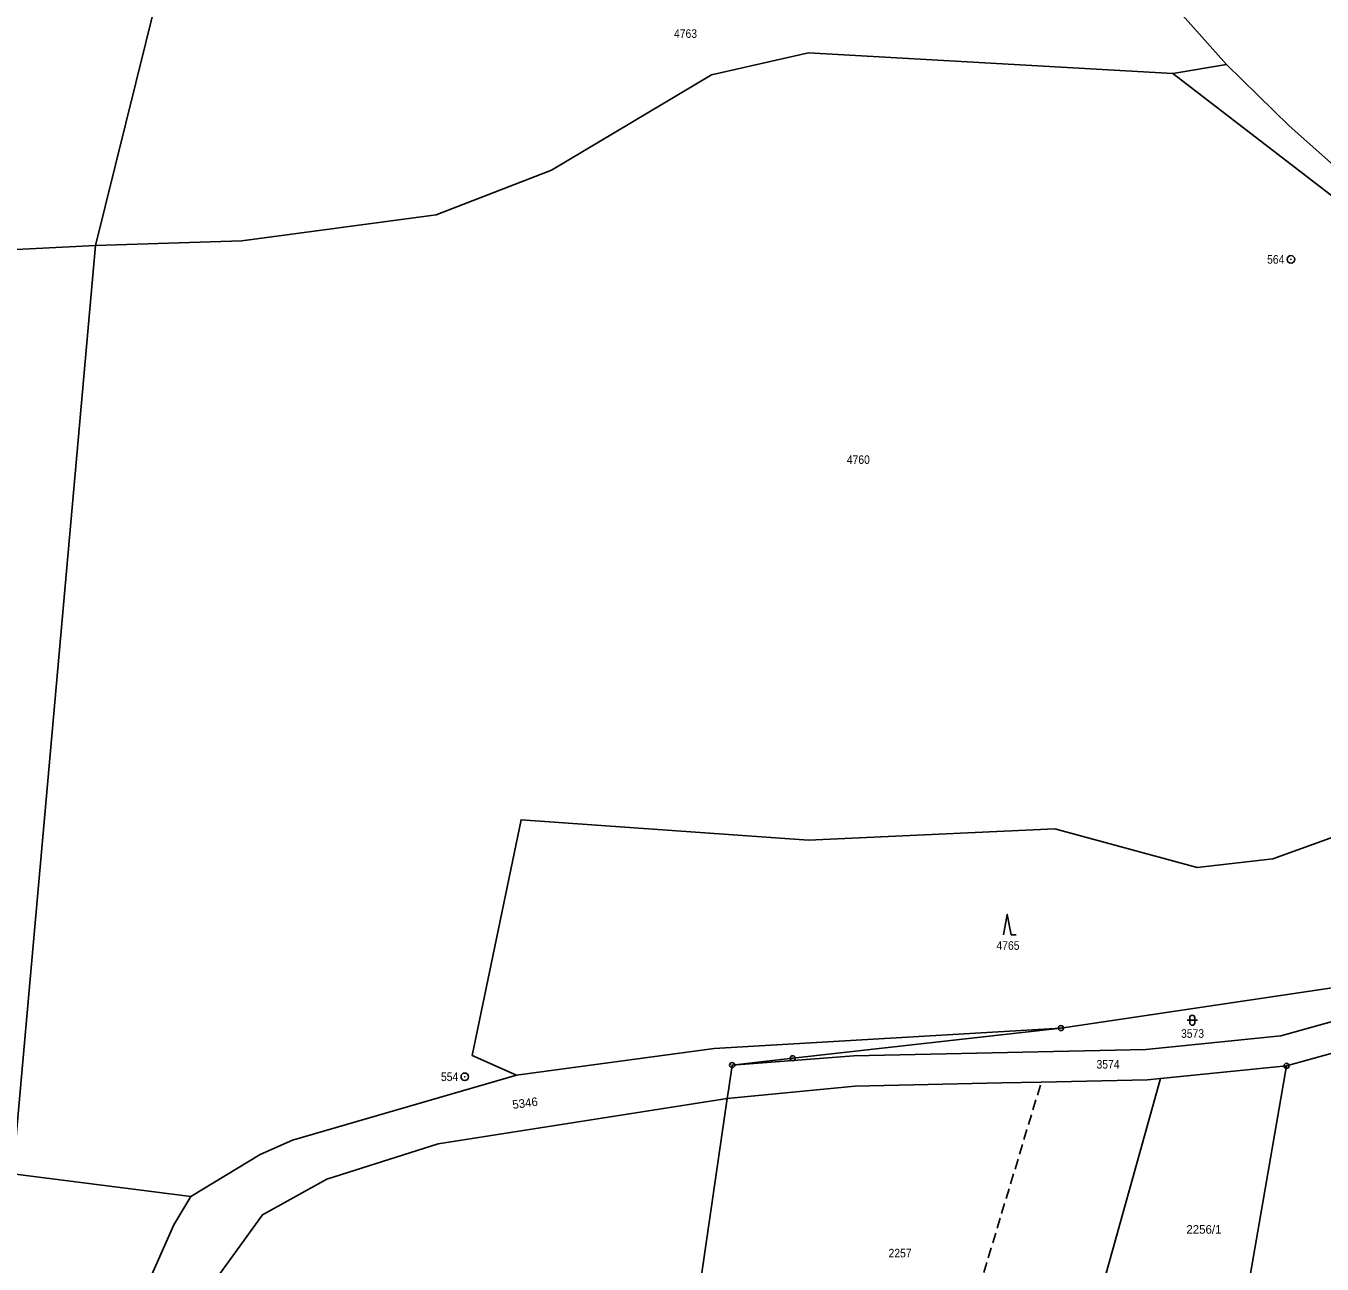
# Model space of a CAD drawing. Extents: x -665688 to -664583, y -1006118 to -1004927.
# Drawn here: x -665448.3 to -665191.6, y -1005645.6 to -1005400.3 of the extents above; entities that cross this region are included whole.
import ezdxf
from ezdxf.enums import TextEntityAlignment as Align

# ---------------------------------------------------------------- set-up
doc = ezdxf.new("R2010")
doc.units = 0
doc.header["$LTSCALE"] = 0.68
doc.linetypes.add('MEDIUM_DASHED', pattern=[4.5, 3, -1.5])
for name, color, linetype, lineweight in [('1', 7, 'Continuous', 25), ('12', 7, 'MEDIUM_DASHED', 25), ('13', 7, 'Continuous', 25), ('24', 7, 'Continuous', 25), ('25', 7, 'Continuous', 25)]:
    doc.layers.add(name, color=color, linetype=linetype, lineweight=lineweight)
doc.layers.add('17', color=7, linetype='Continuous')
doc.layers.add('18', color=7, linetype='Continuous')

msp = doc.modelspace()

# ---------------------------------------------------------------- linework, layer by layer
at = {"layer": '1'}
for p, q in [((-665238, -1005377.08), (-665210.58, -1005407.96)), ((-665434.55, -1005443.84), (-665422.54, -1005395.61)), ((-665308.45, -1005606.17), (-665309.12, -1005610.78)), ((-665223.62, -1005608.84), (-665241.69, -1005673.6)), ((-665309.12, -1005610.78), (-665309.42, -1005612.82))]:
    msp.add_line(p, q, dxfattribs=at)
for points in [[(-665434.55, -1005443.84), (-665405.56, -1005442.93), (-665367.07, -1005437.73), (-665344.22, -1005428.93), (-665312.57, -1005410), (-665293.32, -1005405.67), (-665221.19, -1005409.78)], [(-665136.29, -1005477.24), (-665150.22, -1005460.69), (-665177.15, -1005443.61), (-665221.19, -1005409.78), (-665210.58, -1005407.96)], [(-665210.58, -1005407.96), (-665198.15, -1005420.12), (-665184.6, -1005432.15), (-665168.91, -1005442.94), (-665134.58, -1005458.21), (-665131.02, -1005461.53)], [(-665687.44, -1005437.39), (-665557.36, -1005450.01), (-665434.55, -1005443.84)], [(-665351.13, -1005608.21), (-665395.49, -1005621.05), (-665401.94, -1005623.9), (-665415.62, -1005632.24), (-665450.87, -1005627.72), (-665434.55, -1005443.84)], [(-665160.74, -1005564.98), (-665183.63, -1005558.92), (-665201.39, -1005565.33), (-665216.34, -1005567.05), (-665244.55, -1005559.36), (-665293.31, -1005561.66), (-665350.23, -1005557.59), (-665359.92, -1005604.3), (-665351.13, -1005608.21)], [(-665164.55, -1005594.86), (-665163.78, -1005592.26), (-665164.31, -1005587.01), (-665168.34, -1005587.68), (-665243.35, -1005598.85), (-665296.45, -1005604.83), (-665308.45, -1005606.17)], [(-665308.45, -1005606.17), (-665284.38, -1005604.35), (-665226.56, -1005603.1), (-665199.77, -1005600.41), (-665180.59, -1005595.05), (-665164.31, -1005587.01)], [(-665243.35, -1005598.85), (-665311.98, -1005602.92), (-665351.13, -1005608.21)], [(-665198.65, -1005606.34), (-665209.26, -1005667.29), (-665234.94, -1005803.05), (-665296.22, -1005939.6)], [(-665445.72, -1005770.98), (-665434.59, -1005744.22), (-665427.51, -1005719.43), (-665420.06, -1005676.31), (-665418.1, -1005667.75), (-665412.35, -1005650.92), (-665401.43, -1005635.84), (-665388.69, -1005628.79), (-665366.67, -1005621.78), (-665309.42, -1005612.82)], [(-665415.62, -1005632.24), (-665418.98, -1005637.81), (-665424.38, -1005649.94), (-665432.19, -1005686.1)]]:
    msp.add_lwpolyline(points, dxfattribs=at)
at = {"layer": '12'}
msp.add_lwpolyline([(-665342.78, -1005927.71), (-665327.73, -1005877.55), (-665306.81, -1005807.8), (-665285.04, -1005735.65), (-665263.93, -1005664.85), (-665247.23, -1005609.54)], dxfattribs=at)
at = {"layer": '13'}
for p, q in [((-665198.65, -1005606.34), (-665173.67, -1005599.35)), ((-665223.62, -1005608.84), (-665198.65, -1005606.34)), ((-665309.42, -1005612.82), (-665284.13, -1005610.35)), ((-665284.13, -1005610.35), (-665255.1, -1005609.71)), ((-665255.1, -1005609.71), (-665247.23, -1005609.54)), ((-665247.23, -1005609.54), (-665226.2, -1005609.1)), ((-665226.2, -1005609.1), (-665223.62, -1005608.84)), ((-665315.35, -1005653.48), (-665309.42, -1005612.82))]:
    msp.add_line(p, q, dxfattribs=at)
at = {"layer": '24'}
for centre, radius in [((-665197.8, -1005446.58), 0.75), ((-665197.8, -1005446.58), 0.032), ((-665243.35, -1005598.85), 0.5), ((-665243.35, -1005598.85), 0.032), ((-665296.45, -1005604.83), 0.5), ((-665296.45, -1005604.83), 0.032), ((-665361.39, -1005608.5), 0.75), ((-665308.45, -1005606.17), 0.5), ((-665308.45, -1005606.17), 0.032), ((-665198.65, -1005606.34), 0.5), ((-665198.65, -1005606.34), 0.032), ((-665361.39, -1005608.5), 0.032)]:
    msp.add_circle(centre, radius, dxfattribs=at)
at = {"layer": '25'}
for p, q in [((-665218.33, -1005597.29), (-665216.33, -1005597.29)), ((-665217.83, -1005597.79), (-665217.83, -1005596.79)), ((-665216.83, -1005596.79), (-665216.83, -1005597.79))]:
    msp.add_line(p, q, dxfattribs=at)
msp.add_lwpolyline([(-665254.71, -1005580.35), (-665253.96, -1005576.35), (-665253.21, -1005580.35), (-665252.21, -1005580.35)], dxfattribs=at)
for centre, start, end in [((-665217.33, -1005596.79), 0.101, 180.00143), ((-665217.33, -1005597.79), 180.10243, 0.00286)]:
    msp.add_arc(centre, 0.5, start, end, dxfattribs=at)

# ---------------------------------------------------------------- texts
at = {"layer": '17', "width": 0.9}
for s, p in [('564', (-665199.1, -1005447.43)), ('554', (-665362.69, -1005609.35))]:
    msp.add_text(s, height=1.7, dxfattribs=at).set_placement(p, align=Align.RIGHT)
at = {"layer": '18', "width": 0.9}
for s, p in [('4763', (-665317.6795, -1005402.7)), ('4760', (-665283.4595, -1005487.1)), ('4765', (-665253.8295, -1005583.34)), ('3573', (-665217.2795, -1005600.78)), ('3574', (-665234.0195, -1005606.88)), ('2257', (-665275.1995, -1005644.28))]:
    msp.add_text(s, height=1.7, dxfattribs=at).set_placement(p, align=Align.CENTER)
at = {"layer": '18'}
msp.add_text('5346', height=1.7, rotation=7.6, dxfattribs=at).set_placement((-665349.3509, -1005614.5504), align=Align.CENTER)
msp.add_text('2256/1', height=1.7, dxfattribs=at).set_placement((-665215.0295, -1005639.59), align=Align.CENTER)

doc.saveas('drawing.dxf')
